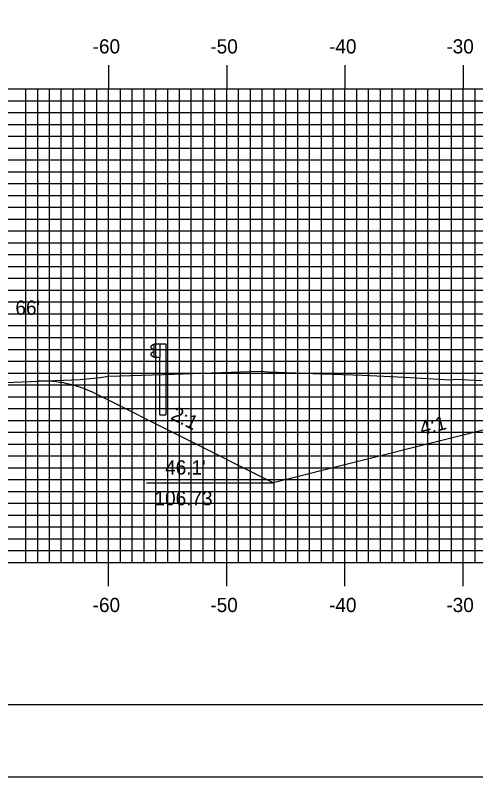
# Model space of a CAD drawing. Extents: x 1684799 to 1685142, y 461260 to 461480.
# Drawn here: x 1684896.8 to 1684935.8, y 461260 to 461324.3 of the extents above; entities that cross this region are included whole.
import ezdxf

# ---------------------------------------------------------------- set-up
doc = ezdxf.new("R2010")
doc.units = 0
for name, color, linetype in [('ANNOTATION', 7, 'Continuous'), ('BORDER', 7, 'Continuous'), ('D_Roadway_SlopeLines', 7, 'Continuous'), ('D_Text_Standard', 7, 'Continuous'), ('H_V ANNOTATION', 7, 'Continuous'), ('M_Roadway_Centerline', 7, 'Continuous'), ('MAJOR', 7, 'Continuous'), ('MINOR', 7, 'Continuous'), ('PDRAIN', 7, 'Continuous'), ('PLOT BOUNDARY', 7, 'Continuous'), ('S_Guardrail_Beam', 7, 'Continuous'), ('S_Roadway_Centerline', 7, 'Continuous')]:
    doc.layers.add(name, color=color, linetype=linetype)

msp = doc.modelspace()

# ---------------------------------------------------------------- linework, layer by layer
at = {"layer": 'BORDER'}
msp.add_lwpolyline([(1684815.116, 461266.072), (1685135.116, 461266.072), (1685135.116, 461476.072), (1684815.116, 461476.072)], close=True, dxfattribs=at)
at = {"layer": 'D_Roadway_SlopeLines'}
for points in [[(1684918.647, 461284.802), (1684903.574, 461292.339)], [(1684946.716, 461291.82), (1684918.647, 461284.802)]]:
    msp.add_lwpolyline(points, dxfattribs=at)
msp.add_arc((1684899.102, 461283.394), 10, 63.43495, 92.24018, dxfattribs=at)
at = {"layer": 'MAJOR'}
for p, q in [((1684904.716, 461320.076), (1684904.716, 461318.072)), ((1684914.716, 461320.076), (1684914.716, 461318.072)), ((1684924.716, 461320.076), (1684924.716, 461318.072)), ((1684934.716, 461320.076), (1684934.716, 461318.072)), ((1684824.716, 461318.072), (1685104.716, 461318.072)), ((1684824.716, 461318.072), (1685104.716, 461318.072)), ((1684904.716, 461278.072), (1684904.716, 461318.072)), ((1684914.716, 461278.072), (1684914.716, 461318.072)), ((1684924.716, 461278.072), (1684924.716, 461318.072)), ((1684934.716, 461278.072), (1684934.716, 461318.072)), ((1684824.716, 461313.072), (1685104.716, 461313.072)), ((1684824.716, 461308.072), (1685104.716, 461308.072)), ((1684824.716, 461303.072), (1685104.716, 461303.072)), ((1684824.716, 461298.072), (1685104.716, 461298.072)), ((1684824.716, 461293.072), (1685104.716, 461293.072)), ((1684824.716, 461288.072), (1685104.716, 461288.072)), ((1684824.716, 461283.072), (1685104.716, 461283.072)), ((1684824.716, 461278.072), (1685104.716, 461278.072)), ((1684824.716, 461278.072), (1685104.716, 461278.072)), ((1684904.716, 461276.068), (1684904.716, 461278.072)), ((1684914.716, 461276.068), (1684914.716, 461278.072)), ((1684924.716, 461276.068), (1684924.716, 461278.072)), ((1684934.716, 461276.068), (1684934.716, 461278.072))]:
    msp.add_line(p, q, dxfattribs=at)
at = {"layer": 'MINOR'}
for p, q in [((1684897.716, 461278.072), (1684897.716, 461318.072)), ((1684898.716, 461278.072), (1684898.716, 461318.072)), ((1684899.716, 461278.072), (1684899.716, 461318.072)), ((1684900.716, 461278.072), (1684900.716, 461318.072)), ((1684901.716, 461278.072), (1684901.716, 461318.072)), ((1684902.716, 461278.072), (1684902.716, 461318.072)), ((1684903.716, 461278.072), (1684903.716, 461318.072)), ((1684905.716, 461278.072), (1684905.716, 461318.072)), ((1684906.716, 461278.072), (1684906.716, 461318.072)), ((1684907.716, 461278.072), (1684907.716, 461318.072)), ((1684908.716, 461278.072), (1684908.716, 461318.072)), ((1684909.716, 461278.072), (1684909.716, 461318.072)), ((1684910.716, 461278.072), (1684910.716, 461318.072)), ((1684911.716, 461278.072), (1684911.716, 461318.072)), ((1684912.716, 461278.072), (1684912.716, 461318.072)), ((1684913.716, 461278.072), (1684913.716, 461318.072)), ((1684915.716, 461278.072), (1684915.716, 461318.072)), ((1684916.716, 461278.072), (1684916.716, 461318.072)), ((1684917.716, 461278.072), (1684917.716, 461318.072)), ((1684918.716, 461278.072), (1684918.716, 461318.072)), ((1684919.716, 461278.072), (1684919.716, 461318.072)), ((1684920.716, 461278.072), (1684920.716, 461318.072)), ((1684921.716, 461278.072), (1684921.716, 461318.072)), ((1684922.716, 461278.072), (1684922.716, 461318.072)), ((1684923.716, 461278.072), (1684923.716, 461318.072)), ((1684925.716, 461278.072), (1684925.716, 461318.072)), ((1684926.716, 461278.072), (1684926.716, 461318.072)), ((1684927.716, 461278.072), (1684927.716, 461318.072)), ((1684928.716, 461278.072), (1684928.716, 461318.072)), ((1684929.716, 461278.072), (1684929.716, 461318.072)), ((1684930.716, 461278.072), (1684930.716, 461318.072)), ((1684931.716, 461278.072), (1684931.716, 461318.072)), ((1684932.716, 461278.072), (1684932.716, 461318.072)), ((1684933.716, 461278.072), (1684933.716, 461318.072)), ((1684935.716, 461278.072), (1684935.716, 461318.072)), ((1684824.716, 461317.072), (1685104.716, 461317.072)), ((1684824.716, 461316.072), (1685104.716, 461316.072)), ((1684824.716, 461315.072), (1685104.716, 461315.072)), ((1684824.716, 461314.072), (1685104.716, 461314.072)), ((1684824.716, 461312.072), (1685104.716, 461312.072)), ((1684824.716, 461311.072), (1685104.716, 461311.072)), ((1684824.716, 461310.072), (1685104.716, 461310.072)), ((1684824.716, 461309.072), (1685104.716, 461309.072)), ((1684824.716, 461307.072), (1685104.716, 461307.072)), ((1684824.716, 461306.072), (1685104.716, 461306.072)), ((1684824.716, 461305.072), (1685104.716, 461305.072)), ((1684824.716, 461304.072), (1685104.716, 461304.072)), ((1684824.716, 461302.072), (1685104.716, 461302.072)), ((1684824.716, 461301.072), (1685104.716, 461301.072)), ((1684824.716, 461300.072), (1685104.716, 461300.072)), ((1684824.716, 461299.072), (1685104.716, 461299.072)), ((1684824.716, 461297.072), (1685104.716, 461297.072)), ((1684824.716, 461296.072), (1685104.716, 461296.072)), ((1684824.716, 461295.072), (1685104.716, 461295.072)), ((1684824.716, 461294.072), (1685104.716, 461294.072)), ((1684824.716, 461292.072), (1685104.716, 461292.072)), ((1684824.716, 461291.072), (1685104.716, 461291.072)), ((1684824.716, 461290.072), (1685104.716, 461290.072)), ((1684824.716, 461289.072), (1685104.716, 461289.072)), ((1684824.716, 461287.072), (1685104.716, 461287.072)), ((1684824.716, 461286.072), (1685104.716, 461286.072)), ((1684824.716, 461285.072), (1685104.716, 461285.072)), ((1684824.716, 461284.072), (1685104.716, 461284.072)), ((1684824.716, 461282.072), (1685104.716, 461282.072)), ((1684824.716, 461281.072), (1685104.716, 461281.072)), ((1684824.716, 461280.072), (1685104.716, 461280.072)), ((1684824.716, 461279.072), (1685104.716, 461279.072))]:
    msp.add_line(p, q, dxfattribs=at)
at = {"layer": 'PDRAIN'}
msp.add_line((1684907.924, 461284.802), (1684918.647, 461284.802), dxfattribs=at)
at = {"layer": 'PLOT BOUNDARY'}
msp.add_lwpolyline([(1684798.93, 461259.954), (1685138.93, 461259.954), (1685138.93, 461479.954), (1684798.93, 461479.954)], close=True, dxfattribs=at)
at = {"layer": 'S_Guardrail_Beam'}
for p, q in [((1684908.47, 461296.446), (1684908.327, 461296.346)), ((1684908.47, 461296.446), (1684908.327, 461296.346)), ((1684908.327, 461296.203), (1684908.522, 461296.067)), ((1684908.327, 461296.203), (1684908.522, 461296.067)), ((1684908.569, 461296.468), (1684908.487, 461296.453)), ((1684908.569, 461296.468), (1684908.487, 461296.453)), ((1684908.569, 461296.541), (1684909.058, 461296.541)), ((1684908.569, 461295.374), (1684908.569, 461296.541)), ((1684908.569, 461296.541), (1684909.058, 461296.541)), ((1684908.569, 461295.374), (1684908.569, 461296.541)), ((1684909.058, 461296.541), (1684909.55, 461296.541)), ((1684909.058, 461296.541), (1684909.058, 461295.374)), ((1684909.058, 461296.541), (1684909.55, 461296.541)), ((1684909.058, 461296.541), (1684909.058, 461295.374)), ((1684909.55, 461296.541), (1684909.55, 461290.541)), ((1684909.55, 461296.541), (1684909.55, 461290.541)), ((1684908.522, 461295.847), (1684908.327, 461295.711)), ((1684908.522, 461295.847), (1684908.327, 461295.711)), ((1684908.327, 461295.568), (1684908.47, 461295.468)), ((1684908.327, 461295.568), (1684908.47, 461295.468)), ((1684908.487, 461295.461), (1684908.569, 461295.447)), ((1684908.487, 461295.461), (1684908.569, 461295.447)), ((1684908.556, 461296.003), (1684908.556, 461295.912)), ((1684908.556, 461296.003), (1684908.556, 461295.912)), ((1684909.058, 461295.374), (1684908.569, 461295.374)), ((1684909.058, 461295.374), (1684908.569, 461295.374)), ((1684909.058, 461290.541), (1684909.058, 461295.374)), ((1684909.058, 461290.541), (1684909.058, 461295.374)), ((1684909.058, 461290.541), (1684909.55, 461290.541)), ((1684909.058, 461290.541), (1684909.55, 461290.541))]:
    msp.add_line(p, q, dxfattribs=at)
for centre, major_axis, start_param, end_param in [((1684908.377, 461296.275), (-0.0877, 0), 5.323254, 7.243116), ((1684908.377, 461296.275), (-0.0877, 0), 5.323254, 7.243116), ((1684908.494, 461296.412), (-0.0417, 0), 4.886922, 5.323254), ((1684908.494, 461296.412), (-0.0417, 0), 4.886922, 5.323254), ((1684908.477, 461296.003), (0.0789, 0), 0, 0.959931), ((1684908.477, 461296.003), (0.0789, 0), 0, 0.959931), ((1684908.377, 461295.64), (-0.0877, 0), 5.323254, 7.243116), ((1684908.377, 461295.64), (-0.0877, 0), 5.323254, 7.243116), ((1684908.494, 461295.502), (-0.0417, 0), 0.959931, 1.396263), ((1684908.494, 461295.502), (-0.0417, 0), 0.959931, 1.396263), ((1684908.477, 461295.912), (0.0789, 0), 5.323254, 6.283185), ((1684908.477, 461295.912), (0.0789, 0), 5.323254, 6.283185)]:
    msp.add_ellipse(centre, major_axis=major_axis, ratio=0.995501, start_param=start_param, end_param=end_param, dxfattribs=at)
at = {"layer": 'S_Roadway_Centerline'}
msp.add_lwpolyline([(1684895.985, 461293.28), (1684902.321, 461293.528), (1684903.991, 461293.706), (1684904.696, 461293.813), (1684904.75, 461293.804), (1684907.501, 461293.881), (1684909.402, 461293.948), (1684917.501, 461294.237), (1684918.277, 461294.166), (1684922.782, 461293.992), (1684926.214, 461293.89), (1684929.757, 461293.727), (1684933.623, 461293.508), (1684934.074, 461293.542), (1684935.179, 461293.501), (1684936.278, 461293.428)], dxfattribs=at)

# ---------------------------------------------------------------- texts
at = {"layer": 'ANNOTATION'}
for s, rotation, p in [('2:1', 333.43495, (1684909.896, 461290.214)), ('4:1', 14.03624, (1684931.217, 461288.806))]:
    msp.add_text(s, height=1.2, rotation=rotation, dxfattribs=at).set_placement(p)
for s, p in [("46.1' ", (1684909.503, 461285.494)), ('106.73', (1684908.603, 461282.894))]:
    msp.add_text(s, height=1.2, dxfattribs=at).set_placement(p)
at = {"layer": 'D_Text_Standard'}
msp.add_text("66'", height=1.2, dxfattribs=at).set_placement((1684896.834, 461298.993))
at = {"layer": 'H_V ANNOTATION'}
for s, p in [('-60', (1684903.368, 461321.072)), ('-50', (1684913.325, 461321.072)), ('-40', (1684923.368, 461321.072)), ('-30', (1684933.293, 461321.072)), ('-60', (1684903.368, 461273.872)), ('-50', (1684913.325, 461273.872)), ('-40', (1684923.368, 461273.872)), ('-30', (1684933.293, 461273.872))]:
    msp.add_text(s, height=1.2, dxfattribs=at).set_placement(p)
at = {"layer": 'M_Roadway_Centerline'}
for s, p in [('C', (1684926.209, 461293.89)), ('L', (1684926.214, 461293.883))]:
    msp.add_text(s, height=0.0146, dxfattribs=at).set_placement(p)

doc.saveas('drawing.dxf')
